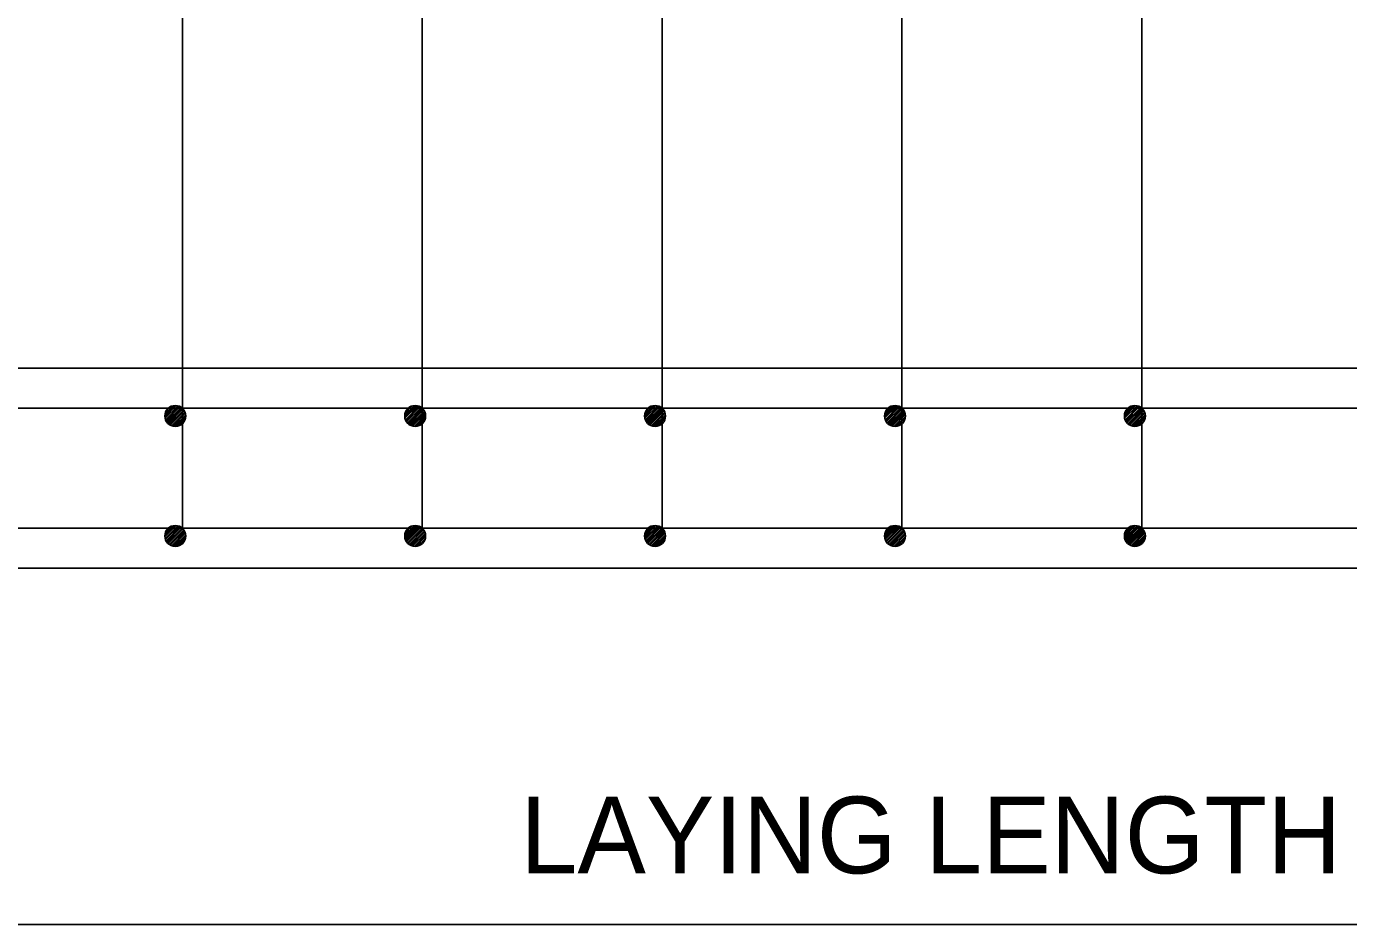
# Model space of a CAD drawing. Extents: x 49991.4 to 50021, y 49987.6 to 50011.4.
# Drawn here: x 50009.872 to 50010.906, y 49996.256 to 49996.958 of the extents above; entities that cross this region are included whole.
import ezdxf

# ---------------------------------------------------------------- set-up
doc = ezdxf.new("R2010")
doc.units = 0
for name, color, linetype in [('Level 1', 7, 'Continuous'), ('Level 2', 7, 'Continuous'), ('Level 3', 7, 'Continuous')]:
    doc.layers.add(name, color=color, linetype=linetype)

msp = doc.modelspace()

# ---------------------------------------------------------------- linework, layer by layer
at = {"layer": 'Level 1'}
for p, q in [((50009.9937, 49997.5976), (50009.9937, 49996.5658)), ((50010.1813, 49997.5976), (50010.1813, 49996.5658)), ((50010.3689, 49997.5976), (50010.3689, 49996.5658)), ((50010.5565, 49997.5976), (50010.5565, 49996.5658)), ((50010.7442, 49997.5976), (50010.7442, 49996.5658)), ((50012.1825, 49996.6909), (50009.337, 49996.6909)), ((50012.1468, 49996.6596), (50009.3683, 49996.6596)), ((50011.9745, 49996.5658), (50009.2433, 49996.5658)), ((50012.0261, 49996.5345), (50009.1807, 49996.5345))]:
    msp.add_line(p, q, dxfattribs=at)
for points in [[(50009.9801, 49996.6528), (50009.9889, 49996.6617)], [(50009.9802, 49996.6542), (50009.9876, 49996.6617)], [(50009.9802, 49996.6517), (50009.9901, 49996.6614)], [(50009.9804, 49996.6558), (50009.9859, 49996.6614)], [(50009.9806, 49996.6506), (50009.991, 49996.6611)], [(50009.981, 49996.6497), (50009.992, 49996.6608)], [(50009.9815, 49996.6489), (50009.9928, 49996.6602)], [(50009.9818, 49996.6585), (50009.9832, 49996.66), (50009.9833, 49996.66)], [(50009.982, 49996.6481), (50009.9821, 49996.6482), (50009.9936, 49996.6597), (50009.9936, 49996.6597)], [(50009.9827, 49996.6474), (50009.9827, 49996.6474), (50009.9942, 49996.659), (50009.9942, 49996.659)], [(50009.9834, 49996.6469), (50009.9948, 49996.6582)], [(50009.9842, 49996.6463), (50009.9954, 49996.6574)], [(50009.9851, 49996.6459), (50009.9958, 49996.6566)], [(50010.1677, 49996.6528), (50010.1765, 49996.6617)], [(50010.1678, 49996.6542), (50010.1752, 49996.6617)], [(50010.1678, 49996.6517), (50010.1777, 49996.6614)], [(50010.168, 49996.6558), (50010.1735, 49996.6614)], [(50010.1682, 49996.6506), (50010.1786, 49996.6611)], [(50010.1686, 49996.6497), (50010.1796, 49996.6608)], [(50010.1691, 49996.6489), (50010.1804, 49996.6602)], [(50010.1694, 49996.6585), (50010.1708, 49996.66), (50010.1709, 49996.66)], [(50010.1696, 49996.6481), (50010.1697, 49996.6482), (50010.1812, 49996.6597), (50010.1812, 49996.6597)], [(50010.1703, 49996.6474), (50010.1703, 49996.6474), (50010.1818, 49996.659), (50010.1818, 49996.659)], [(50010.171, 49996.6469), (50010.1824, 49996.6582)], [(50010.1718, 49996.6463), (50010.183, 49996.6574)], [(50010.1727, 49996.6459), (50010.1834, 49996.6566)], [(50010.3553, 49996.6528), (50010.3641, 49996.6617)], [(50010.3554, 49996.6542), (50010.3628, 49996.6617)], [(50010.3554, 49996.6517), (50010.3653, 49996.6614)], [(50010.3556, 49996.6558), (50010.3611, 49996.6614)], [(50010.3558, 49996.6506), (50010.3663, 49996.6611)], [(50010.3562, 49996.6497), (50010.3672, 49996.6608)], [(50010.3567, 49996.6489), (50010.368, 49996.6602)], [(50010.357, 49996.6585), (50010.3584, 49996.66), (50010.3586, 49996.66)], [(50010.3572, 49996.6481), (50010.3573, 49996.6482), (50010.3688, 49996.6597), (50010.3689, 49996.6597)], [(50010.3579, 49996.6474), (50010.3579, 49996.6474), (50010.3694, 49996.659), (50010.3694, 49996.659)], [(50010.3586, 49996.6469), (50010.37, 49996.6582)], [(50010.3594, 49996.6463), (50010.3706, 49996.6574)], [(50010.3603, 49996.6459), (50010.371, 49996.6566)], [(50010.5429, 49996.6528), (50010.5517, 49996.6617)], [(50010.543, 49996.6542), (50010.5504, 49996.6617)], [(50010.543, 49996.6517), (50010.5529, 49996.6614)], [(50010.5432, 49996.6558), (50010.5488, 49996.6614)], [(50010.5434, 49996.6506), (50010.5539, 49996.6611)], [(50010.5438, 49996.6497), (50010.5548, 49996.6608)], [(50010.5443, 49996.6489), (50010.5556, 49996.6602)], [(50010.5446, 49996.6585), (50010.546, 49996.66), (50010.5462, 49996.66)], [(50010.5448, 49996.6481), (50010.5449, 49996.6482), (50010.5564, 49996.6597), (50010.5565, 49996.6597)], [(50010.5455, 49996.6474), (50010.5455, 49996.6474), (50010.557, 49996.659), (50010.557, 49996.659)], [(50010.5462, 49996.6469), (50010.5577, 49996.6582)], [(50010.547, 49996.6463), (50010.5582, 49996.6574)], [(50010.5479, 49996.6459), (50010.5586, 49996.6566)], [(50010.7305, 49996.6528), (50010.7393, 49996.6617)], [(50010.7306, 49996.6542), (50010.738, 49996.6617)], [(50010.7306, 49996.6517), (50010.7405, 49996.6614)], [(50010.7308, 49996.6558), (50010.7364, 49996.6614)], [(50010.731, 49996.6506), (50010.7415, 49996.6611)], [(50010.7314, 49996.6497), (50010.7424, 49996.6608)], [(50010.7319, 49996.6489), (50010.7433, 49996.6602)], [(50010.7322, 49996.6585), (50010.7336, 49996.66), (50010.7338, 49996.66)], [(50010.7324, 49996.6481), (50010.7325, 49996.6482), (50010.744, 49996.6597), (50010.7441, 49996.6597)], [(50010.7331, 49996.6474), (50010.7331, 49996.6474), (50010.7447, 49996.659), (50010.7447, 49996.659)], [(50010.7338, 49996.6469), (50010.7453, 49996.6582)], [(50010.7346, 49996.6463), (50010.7458, 49996.6574)], [(50010.7355, 49996.6459), (50010.7462, 49996.6566)], [(50009.9862, 49996.6456), (50009.9962, 49996.6556)], [(50009.9873, 49996.6454), (50009.9963, 49996.6545)], [(50009.9886, 49996.6454), (50009.9964, 49996.6532)], [(50009.9901, 49996.6455), (50009.9962, 49996.6517)], [(50009.9922, 49996.6463), (50009.9954, 49996.6495)], [(50010.1738, 49996.6456), (50010.1838, 49996.6556)], [(50010.1749, 49996.6454), (50010.1839, 49996.6545)], [(50010.1762, 49996.6454), (50010.184, 49996.6532)], [(50010.1777, 49996.6455), (50010.1838, 49996.6517)], [(50010.1798, 49996.6463), (50010.183, 49996.6495)], [(50010.3614, 49996.6456), (50010.3714, 49996.6556)], [(50010.3625, 49996.6454), (50010.3715, 49996.6545)], [(50010.3638, 49996.6454), (50010.3716, 49996.6532)], [(50010.3653, 49996.6455), (50010.3714, 49996.6517)], [(50010.3674, 49996.6463), (50010.3706, 49996.6495)], [(50010.549, 49996.6456), (50010.559, 49996.6556)], [(50010.5501, 49996.6454), (50010.5591, 49996.6545)], [(50010.5514, 49996.6454), (50010.5592, 49996.6532)], [(50010.5529, 49996.6455), (50010.559, 49996.6517)], [(50010.555, 49996.6463), (50010.5582, 49996.6495)], [(50010.7366, 49996.6456), (50010.7466, 49996.6556)], [(50010.7377, 49996.6454), (50010.7467, 49996.6545)], [(50010.739, 49996.6454), (50010.7468, 49996.6532)], [(50010.7405, 49996.6455), (50010.7466, 49996.6517)], [(50010.7426, 49996.6463), (50010.7458, 49996.6495)], [(50009.9801, 49996.559), (50009.9889, 49996.5678)], [(50009.9802, 49996.5603), (50009.9876, 49996.5678)], [(50009.9802, 49996.5578), (50009.9901, 49996.5677)], [(50009.9804, 49996.562), (50009.9859, 49996.5675)], [(50009.9806, 49996.5568), (50009.991, 49996.5674)], [(50009.981, 49996.5559), (50009.992, 49996.567)], [(50009.9815, 49996.5551), (50009.9928, 49996.5665)], [(50009.9818, 49996.5646), (50009.9832, 49996.5662), (50009.9833, 49996.5662)], [(50009.982, 49996.5542), (50009.9821, 49996.5543), (50009.9936, 49996.5659), (50009.9936, 49996.5659)], [(50009.9827, 49996.5537), (50009.9827, 49996.5537), (50009.9942, 49996.5652), (50009.9942, 49996.5652)], [(50009.9834, 49996.5531), (50009.9948, 49996.5645)], [(50009.9842, 49996.5526), (50009.9954, 49996.5637)], [(50009.9851, 49996.5521), (50009.9958, 49996.5628)], [(50010.1677, 49996.559), (50010.1765, 49996.5678)], [(50010.1678, 49996.5603), (50010.1752, 49996.5678)], [(50010.1678, 49996.5578), (50010.1777, 49996.5677)], [(50010.168, 49996.562), (50010.1735, 49996.5675)], [(50010.1682, 49996.5568), (50010.1786, 49996.5674)], [(50010.1686, 49996.5559), (50010.1796, 49996.567)], [(50010.1691, 49996.5551), (50010.1804, 49996.5665)], [(50010.1694, 49996.5646), (50010.1708, 49996.5662), (50010.1709, 49996.5662)], [(50010.1696, 49996.5542), (50010.1697, 49996.5543), (50010.1812, 49996.5659), (50010.1812, 49996.5659)], [(50010.1703, 49996.5537), (50010.1703, 49996.5537), (50010.1818, 49996.5652), (50010.1818, 49996.5652)], [(50010.171, 49996.5531), (50010.1824, 49996.5645)], [(50010.1718, 49996.5526), (50010.183, 49996.5637)], [(50010.1727, 49996.5521), (50010.1834, 49996.5628)], [(50010.3553, 49996.559), (50010.3641, 49996.5678)], [(50010.3554, 49996.5603), (50010.3628, 49996.5678)], [(50010.3554, 49996.5578), (50010.3653, 49996.5677)], [(50010.3556, 49996.562), (50010.3611, 49996.5675)], [(50010.3558, 49996.5568), (50010.3663, 49996.5674)], [(50010.3562, 49996.5559), (50010.3672, 49996.567)], [(50010.3567, 49996.5551), (50010.368, 49996.5665)], [(50010.357, 49996.5646), (50010.3584, 49996.5662), (50010.3586, 49996.5662)], [(50010.3572, 49996.5542), (50010.3573, 49996.5543), (50010.3688, 49996.5659), (50010.3689, 49996.5659)], [(50010.3579, 49996.5537), (50010.3579, 49996.5537), (50010.3694, 49996.5652), (50010.3694, 49996.5652)], [(50010.3586, 49996.5531), (50010.37, 49996.5645)], [(50010.3594, 49996.5526), (50010.3706, 49996.5637)], [(50010.3603, 49996.5521), (50010.371, 49996.5628)], [(50010.5429, 49996.559), (50010.5517, 49996.5678)], [(50010.543, 49996.5603), (50010.5504, 49996.5678)], [(50010.543, 49996.5578), (50010.5529, 49996.5677)], [(50010.5432, 49996.562), (50010.5488, 49996.5675)], [(50010.5434, 49996.5568), (50010.5539, 49996.5674)], [(50010.5438, 49996.5559), (50010.5548, 49996.567)], [(50010.5443, 49996.5551), (50010.5556, 49996.5665)], [(50010.5446, 49996.5646), (50010.546, 49996.5662), (50010.5462, 49996.5662)], [(50010.5448, 49996.5542), (50010.5449, 49996.5543), (50010.5564, 49996.5659), (50010.5565, 49996.5659)], [(50010.5455, 49996.5537), (50010.5455, 49996.5537), (50010.557, 49996.5652), (50010.557, 49996.5652)], [(50010.5462, 49996.5531), (50010.5577, 49996.5645)], [(50010.547, 49996.5526), (50010.5582, 49996.5637)], [(50010.5479, 49996.5521), (50010.5586, 49996.5628)], [(50010.7305, 49996.559), (50010.7393, 49996.5678)], [(50010.7306, 49996.5603), (50010.738, 49996.5678)], [(50010.7306, 49996.5578), (50010.7405, 49996.5677)], [(50010.7308, 49996.562), (50010.7364, 49996.5675)], [(50010.731, 49996.5568), (50010.7415, 49996.5674)], [(50010.7314, 49996.5559), (50010.7424, 49996.567)], [(50010.7319, 49996.5551), (50010.7433, 49996.5665)], [(50010.7322, 49996.5646), (50010.7336, 49996.5662), (50010.7338, 49996.5662)], [(50010.7324, 49996.5542), (50010.7325, 49996.5543), (50010.744, 49996.5659), (50010.7441, 49996.5659)], [(50010.7331, 49996.5537), (50010.7331, 49996.5537), (50010.7447, 49996.5652), (50010.7447, 49996.5652)], [(50010.7338, 49996.5531), (50010.7453, 49996.5645)], [(50010.7346, 49996.5526), (50010.7458, 49996.5637)], [(50010.7355, 49996.5521), (50010.7462, 49996.5628)], [(50009.9862, 49996.5518), (50009.9962, 49996.5618)], [(50009.9873, 49996.5515), (50009.9963, 49996.5606)], [(50009.9886, 49996.5515), (50009.9964, 49996.5594)], [(50009.9901, 49996.5517), (50009.9962, 49996.5578)], [(50009.9922, 49996.5526), (50009.9954, 49996.5557)], [(50010.1738, 49996.5518), (50010.1838, 49996.5618)], [(50010.1749, 49996.5515), (50010.1839, 49996.5606)], [(50010.1762, 49996.5515), (50010.184, 49996.5594)], [(50010.1777, 49996.5517), (50010.1838, 49996.5578)], [(50010.1798, 49996.5526), (50010.183, 49996.5557)], [(50010.3614, 49996.5518), (50010.3714, 49996.5618)], [(50010.3625, 49996.5515), (50010.3715, 49996.5606)], [(50010.3638, 49996.5515), (50010.3716, 49996.5594)], [(50010.3653, 49996.5517), (50010.3714, 49996.5578)], [(50010.3674, 49996.5526), (50010.3706, 49996.5557)], [(50010.549, 49996.5518), (50010.559, 49996.5618)], [(50010.5501, 49996.5515), (50010.5591, 49996.5606)], [(50010.5514, 49996.5515), (50010.5592, 49996.5594)], [(50010.5529, 49996.5517), (50010.559, 49996.5578)], [(50010.555, 49996.5526), (50010.5582, 49996.5557)], [(50010.7366, 49996.5518), (50010.7466, 49996.5618)], [(50010.7377, 49996.5515), (50010.7467, 49996.5606)], [(50010.739, 49996.5515), (50010.7468, 49996.5594)], [(50010.7405, 49996.5517), (50010.7466, 49996.5578)], [(50010.7426, 49996.5526), (50010.7458, 49996.5557)]]:
    msp.add_lwpolyline(points, dxfattribs=at)
for centre in [(50009.9882, 49996.6535), (50010.1758, 49996.6535), (50010.3634, 49996.6535), (50010.5511, 49996.6535), (50010.7387, 49996.6535), (50009.9882, 49996.5597), (50010.1758, 49996.5597), (50010.3634, 49996.5597), (50010.5511, 49996.5597), (50010.7387, 49996.5597)]:
    msp.add_circle(centre, 0.00819, dxfattribs=at)
at = {"layer": 'Level 3'}
msp.add_line((50009.1807, 49996.2559), (50012.0261, 49996.2559), dxfattribs=at)

# ---------------------------------------------------------------- texts
at = {"layer": 'Level 2'}
msp.add_text('LAYING LENGTH', height=0.06, dxfattribs=at).set_placement((50010.2581, 49996.2959))

doc.saveas('drawing.dxf')
